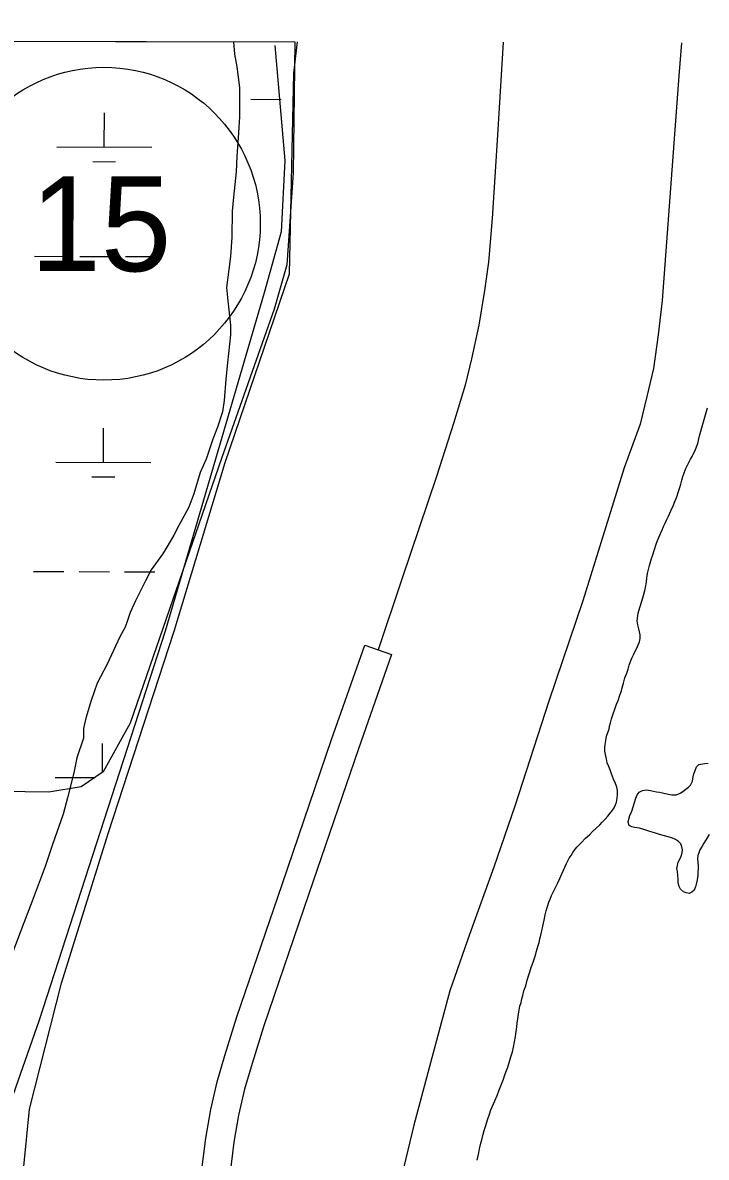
# Model space of a CAD drawing. Extents: x 3172297 to 3210190, y 958463 to 983887.
# Drawn here: x 3187707 to 3188429, y 980905 to 982102 of the extents above; entities that cross this region are included whole.
import ezdxf

# ---------------------------------------------------------------- set-up
doc = ezdxf.new("R2010")
doc.units = 0
for name, color, linetype in [('V-LEVE-TOET', 7, 'Continuous'), ('V-ROAD-CNTR', 7, 'Continuous'), ('V-ROAD-IDEN', 7, 'Continuous'), ('V-SITE-VEGE', 7, 'Continuous'), ('V-TOPO-SHOR', 7, 'Continuous'), ('V-WETL-SWMP', 7, 'Continuous')]:
    doc.layers.add(name, color=color, linetype=linetype)

msp = doc.modelspace()

# ---------------------------------------------------------------- linework, layer by layer
at = {"layer": 'V-LEVE-TOET'}
for points in [[(3187693.8, 980749.4), (3187714.4, 980955.7), (3187747.9, 981088.4), (3187797.2, 981246.3), (3187867, 981459.9), (3187920.8, 981637.7), (3187988.7, 981836.8), (3187993.1, 982048.3), (3187997.1, 982081.4)], [(3188402.5, 982080.4), (3188399.6, 982045.6), (3188390.7, 981926.9), (3188382, 981808.7), (3188377.9, 981772.3), (3188372.8, 981736.9), (3188365.8, 981707.4), (3188358.9, 981678.2), (3188342, 981632.2), (3188298.1, 981491.7), (3188262.4, 981386.1), (3188226.3, 981275.3), (3188204.4, 981210.9), (3188178.7, 981139.9), (3188158, 981080.6), (3188137.5, 981004.7), (3188120, 980938.8), (3188109.2, 980894.7)]]:
    msp.add_lwpolyline(points, dxfattribs=at)
at = {"layer": 'V-ROAD-CNTR'}
for points in [[(3188214, 982080.8), (3188208.3, 981982.9), (3188202.6, 981895), (3188198.6, 981848.9), (3188194.3, 981819), (3188188.4, 981782.5), (3188180.8, 981747), (3188174, 981719.2), (3188161.9, 981678.9), (3188143.8, 981623), (3188107.1, 981514.5), (3188082.1, 981440.1)], [(3187895.8, 980889.3), (3187900.3, 980925.2), (3187905.5, 980955.2), (3187912.2, 980984.5), (3187920.3, 981012.3), (3187932.9, 981053), (3187980.8, 981192.6), (3188033.1, 981345.5), (3188068, 981445.1), (3188096.3, 981435.2), (3188061.4, 981335.7), (3188009.1, 981182.9), (3187961.4, 981043.7), (3187949.1, 981003.7), (3187941.2, 980976.9), (3187934.9, 980949.3), (3187930, 980920.8), (3187925.6, 980886.1)]]:
    msp.add_lwpolyline(points, dxfattribs=at)
at = {"layer": 'V-ROAD-IDEN'}
msp.add_circle((3187792.8, 981889.5), 165, dxfattribs=at)
msp.add_circle((3187792.8, 981889.5), 165, dxfattribs=at)
at = {"layer": 'V-SITE-VEGE'}
for p, q in [((3179852.6, 982101.5), (3187929.6, 982081.5)), ((3187929.6, 982081.5), (3187930.7, 982068.2)), ((3187930.7, 982068.2), (3187933, 982054.9)), ((3187933, 982054.9), (3187935.9, 982033)), ((3187935.9, 982033), (3187935.7, 982002.6)), ((3187935.7, 982002.6), (3187934.8, 981985.4)), ((3187934.8, 981985.4), (3187933.1, 981960.5)), ((3187933.1, 981960.5), (3187932.2, 981944.1)), ((3187932.2, 981944.1), (3187929.7, 981917.5)), ((3187929.7, 981917.5), (3187928, 981902.7)), ((3187928, 981902.7), (3187927.9, 981875.4)), ((3187927.9, 981875.4), (3187926.2, 981855.1)), ((3187926.2, 981855.1), (3187924.5, 981841.1)), ((3187924.5, 981841.1), (3187922.1, 981822.3)), ((3187922.1, 981822.3), (3187923.5, 981808.3)), ((3187923.5, 981808.3), (3187926.5, 981782.5)), ((3187926.5, 981782.5), (3187926.4, 981772.3)), ((3187926.4, 981772.3), (3187923.1, 981742.7)), ((3187923.1, 981742.7), (3187921.4, 981725.5)), ((3187921.4, 981725.5), (3187919.7, 981702.9)), ((3187919.7, 981702.9), (3187918.1, 981691.2)), ((3187918.1, 981691.2), (3187912.5, 981674.8)), ((3187912.5, 981674.8), (3187907.7, 981662.4)), ((3187907.7, 981662.4), (3187900.6, 981641.3)), ((3187900.6, 981641.3), (3187894.2, 981627.3)), ((3187894.2, 981627.3), (3187887.8, 981604.7)), ((3187887.8, 981604.7), (3187882.3, 981590.7)), ((3187882.3, 981590.7), (3187872, 981571.3)), ((3187872, 981571.3), (3187866.5, 981561.2)), ((3187866.5, 981561.2), (3187860.1, 981550.3)), ((3187860.1, 981550.3), (3187854.6, 981540.9)), ((3187854.6, 981540.9), (3187842.8, 981524.6)), ((3187842.8, 981524.6), (3187836.5, 981513)), ((3187836.5, 981513), (3187826.2, 981491.9)), ((3187826.2, 981491.9), (3187820.6, 981479.5)), ((3187820.6, 981479.5), (3187817.5, 981470.9)), ((3187815.1, 981463.9), (3187809.5, 981453.8)), ((3187817.5, 981470.9), (3187815.1, 981463.9)), ((3187809.5, 981453.8), (3187796.1, 981425)), ((3187796.1, 981425), (3187785.8, 981404.8)), ((3187785.8, 981404.8), (3187779.4, 981386.8)), ((3187779.4, 981386.8), (3187773.8, 981368.1)), ((3187773.8, 981368.1), (3187771.4, 981357.2)), ((3187771.4, 981357.2), (3187771.4, 981347.1)), ((3187771.4, 981347.1), (3187764.2, 981326.1)), ((3187764.2, 981326.1), (3187761, 981310.5)), ((3187761, 981310.5), (3187754.5, 981284)), ((3187754.5, 981284), (3187749.7, 981266.8)), ((3187749.7, 981266.8), (3187738.6, 981234.9)), ((3187738.6, 981234.9), (3187730.6, 981211.5)), ((3187730.6, 981211.5), (3187717.1, 981174.9)), ((3187717.1, 981174.9), (3187708.4, 981152.3)), ((3187708.4, 981152.3), (3187695.7, 981118.8))]:
    msp.add_line(p, q, dxfattribs=at)
at = {"layer": 'V-TOPO-SHOR'}
for points in [[(3187973.3, 982077.4), (3187983.7, 981956), (3187980, 981881), (3187962, 981816.7), (3187857.5, 981459.9), (3187724.4, 981049.6), (3187674, 980906.8)], [(3188321.5, 981333.1), (3188321.4, 981337), (3188321.8, 981340.2), (3188322.5, 981344.5), (3188323.3, 981348.9), (3188324.7, 981353), (3188325.9, 981356.6), (3188326.4, 981359.6), (3188327.3, 981363), (3188328.5, 981367.3), (3188329.9, 981371.7), (3188332.2, 981378.5), (3188333.9, 981382.8), (3188335.5, 981386.5), (3188337.4, 981392.2), (3188339, 981396.9), (3188339.9, 981400.1), (3188341.1, 981404.9), (3188342.7, 981410.4), (3188344.6, 981415.6), (3188346, 981419.8), (3188347.2, 981423.9), (3188348.6, 981427.7), (3188350, 981431.4), (3188352.1, 981435.7), (3188353.5, 981438.7), (3188355.1, 981441.8), (3188356.7, 981445.5), (3188357.9, 981448.7), (3188358.6, 981451.9), (3188358.6, 981456), (3188358, 981459), (3188357.3, 981462.1), (3188356.2, 981466.3), (3188355.6, 981470.6), (3188356, 981473.6), (3188356.8, 981478.8), (3188358.5, 981484.8), (3188360.6, 981491.4), (3188362.4, 981497.3), (3188363.6, 981502.8), (3188364.5, 981505.9), (3188365.3, 981511.4), (3188365.8, 981516.2), (3188366.5, 981520.5), (3188367.2, 981523.5), (3188368.6, 981529.2), (3188370.7, 981536.3), (3188371.7, 981539.2), (3188373.8, 981545.8), (3188375.7, 981551.5), (3188377.1, 981555.4), (3188378.4, 981558.4), (3188380.5, 981563.6), (3188382.2, 981567.5), (3188383.4, 981570.3), (3188385, 981573.7), (3188386.4, 981576.8), (3188388.7, 981581.1), (3188391, 981586.8), (3188393.6, 981592.1), (3188395.5, 981596.4), (3188396.9, 981599.6), (3188397.8, 981602.6), (3188398.9, 981606), (3188400.6, 981611.4), (3188401.6, 981614.9), (3188402.7, 981619), (3188403.7, 981622.8), (3188404.8, 981625.8), (3188406.7, 981630.6), (3188408.5, 981634), (3188409.7, 981636.8), (3188412, 981641.1), (3188413.6, 981644), (3188415, 981647), (3188416.4, 981649.7), (3188419.5, 981657.7), (3188421.2, 981665.9), (3188429.7, 981695.3)], [(3188186.6, 980901.9), (3188187.6, 980906.5), (3188188.5, 980909.5), (3188189.3, 980913.8), (3188190.7, 980919.9), (3188191.9, 980924.7), (3188193.2, 980929.3), (3188194.2, 980933.2), (3188195.8, 980938.6), (3188197.7, 980944.5), (3188199.6, 980950.3), (3188201.3, 980954.8), (3188202.7, 980958.2), (3188205.4, 980964.3), (3188207.7, 980970.1), (3188209.6, 980974.9), (3188211, 980978.5), (3188213.1, 980983.7), (3188214.5, 980987.4), (3188216, 980991.9), (3188217.8, 980996.5), (3188219, 980999.9), (3188220.9, 981006), (3188222.3, 981010.8), (3188223.9, 981016.1), (3188224.9, 981021.1), (3188226.1, 981026.6), (3188227.2, 981032.3), (3188227.8, 981037.5), (3188228.4, 981042.5), (3188228.9, 981046.2), (3188229.7, 981050.8), (3188230.2, 981055.8), (3188231.1, 981060.1), (3188231.9, 981064.2), (3188233, 981068.1), (3188234, 981072.2), (3188234.9, 981075.6), (3188236.1, 981080.4), (3188237.9, 981085.6), (3188239.4, 981091.8), (3188241.5, 981098.4), (3188243.8, 981105.2), (3188246.2, 981111.8), (3188247.8, 981116.9), (3188249.5, 981122.3), (3188250.9, 981127.3), (3188252.1, 981131.3), (3188253, 981135.4), (3188253.9, 981139.2), (3188254.9, 981143.6), (3188256, 981148.8), (3188257.3, 981154.9), (3188258.4, 981160.7), (3188259.4, 981164.7), (3188260.8, 981169.5), (3188262.2, 981174.1), (3188263.6, 981177.1), (3188265.3, 981181), (3188266.4, 981183.9), (3188268.2, 981187.5), (3188270.3, 981191.7), (3188271.7, 981194.4), (3188274.1, 981199.1), (3188276.2, 981203.9), (3188277.8, 981207.6), (3188279.2, 981210.8), (3188281.1, 981214.6), (3188282.5, 981217.4), (3188283.9, 981220.3), (3188285.9, 981223.3), (3188287.8, 981226.4), (3188290.3, 981229.9), (3188292.2, 981232.3), (3188296.3, 981236.5), (3188301.1, 981241.4), (3188305.1, 981245.1), (3188308.5, 981248.4), (3188311.8, 981251.6), (3188316.1, 981255.5), (3188318.7, 981258.2), (3188321.9, 981261.6), (3188324.7, 981264.8), (3188327, 981267.7), (3188329, 981270), (3188331.4, 981273.6), (3188332.8, 981276.6), (3188333.9, 981279.6), (3188334.4, 981283.6), (3188334.9, 981287.3), (3188334.9, 981291.7), (3188334.1, 981295.3), (3188332.7, 981299), (3188330.7, 981303.8), (3188328.5, 981309.3), (3188327.1, 981313.6), (3188325.7, 981316.9), (3188324, 981320.8), (3188323.1, 981325.3), (3188322.2, 981329.7), (3188321.5, 981333.1)], [(3188431.4, 981245.2), (3188428.4, 981240.1), (3188425.9, 981236.1), (3188424, 981233.1), (3188421.7, 981229.3), (3188420.7, 981226.1), (3188419.6, 981223.1), (3188419.3, 981220.1), (3188419.5, 981215.6), (3188419.9, 981212.3), (3188419.9, 981209.2), (3188419.7, 981206), (3188419.6, 981202.1), (3188418.9, 981197.5), (3188417.8, 981193), (3188417.2, 981190), (3188415.9, 981186.6), (3188413.3, 981184.5), (3188410.4, 981183.2), (3188407.4, 981183.7), (3188404.6, 981184.8), (3188401.3, 981187.8), (3188399.9, 981190.4), (3188398.8, 981194.5), (3188398.8, 981198.6), (3188398.4, 981202.2), (3188398.2, 981206.3), (3188397.6, 981209.5), (3188398, 981212.8), (3188399, 981216), (3188400.6, 981219.3), (3188402, 981222.6), (3188403.1, 981226), (3188403.4, 981229.1), (3188402.8, 981232.4), (3188401.7, 981235.6), (3188399.2, 981238.1), (3188396.2, 981240), (3188392.8, 981241.4), (3188388.4, 981242.8), (3188384.4, 981244), (3188379.3, 981245.3), (3188373.9, 981247), (3188369.1, 981248.6), (3188363.6, 981250.3), (3188357.9, 981251.9), (3188352.9, 981252.7), (3188349.9, 981253.6), (3188347.2, 981255), (3188345.9, 981258.2), (3188346.8, 981261.4), (3188348, 981265.3), (3188350, 981269.8), (3188351.5, 981274.6), (3188352.6, 981279.1), (3188354, 981283.7), (3188355.7, 981287.3), (3188357.8, 981290.1), (3188361.2, 981291.9), (3188365.5, 981292.3), (3188369.7, 981291.6), (3188376.1, 981290.4), (3188379.2, 981289.9), (3188382.4, 981289.2), (3188387, 981288.2), (3188392.3, 981287.3), (3188396.8, 981287.3), (3188401.1, 981289), (3188403.7, 981290.6), (3188406.9, 981293.1), (3188409.7, 981295.2), (3188412, 981297.4), (3188413.8, 981301.7), (3188414.6, 981306.1), (3188415.5, 981309.5), (3188416.9, 981312.9), (3188418.1, 981316.8), (3188420.8, 981319), (3188427, 981320.2), (3188430.5, 981320.6)]]:
    msp.add_lwpolyline(points, dxfattribs=at)
at = {"layer": 'V-WETL-SWMP'}
for p, q in [((3182545.3, 982094.9), (3187994.3, 982081.4)), ((3187994.3, 982081.4), (3187992.6, 981943)), ((3187947.9, 982020.7), (3187979.9, 982020.6)), ((3187793.2, 981970.4), (3187793.3, 982006.4)), ((3187743.2, 981970.5), (3187843.2, 981970.3)), ((3187781.1, 981955), (3187805.1, 981954.9)), ((3187992.6, 981943), (3187986, 981846)), ((3187719.4, 981855.2), (3187751.4, 981855.1)), ((3187767.4, 981855.1), (3187799.4, 981855)), ((3187815.4, 981855), (3187847.4, 981854.9)), ((3187986, 981846), (3187972.6, 981799.4)), ((3187972.6, 981799.4), (3187917.2, 981642.9)), ((3187792.2, 981637.9), (3187792.3, 981673.9)), ((3187917.2, 981642.9), (3187820.5, 981362.7)), ((3187742.2, 981638), (3187842.2, 981637.8)), ((3187780.2, 981622.5), (3187804.2, 981622.5)), ((3187718.5, 981522.7), (3187750.5, 981522.6)), ((3187766.5, 981522.6), (3187798.5, 981522.5)), ((3187814.5, 981522.5), (3187846.5, 981522.4)), ((3187820.5, 981362.7), (3187792, 981311.4)), ((3187791.2, 981310.9), (3187791.3, 981341.4)), ((3187792, 981311.4), (3187768.9, 981295.7)), ((3187768.9, 981295.7), (3187734.7, 981290)), ((3187741.2, 981305.5), (3187783.2, 981305.4)), ((3187734.7, 981290), (3187684.8, 981290.7))]:
    msp.add_line(p, q, dxfattribs=at)

# ---------------------------------------------------------------- texts
at = {"layer": 'V-ROAD-IDEN'}
msp.add_text('15', height=100, rotation=359.8583, dxfattribs=at).set_placement((3187715.1, 981839.7))

doc.saveas('drawing.dxf')
